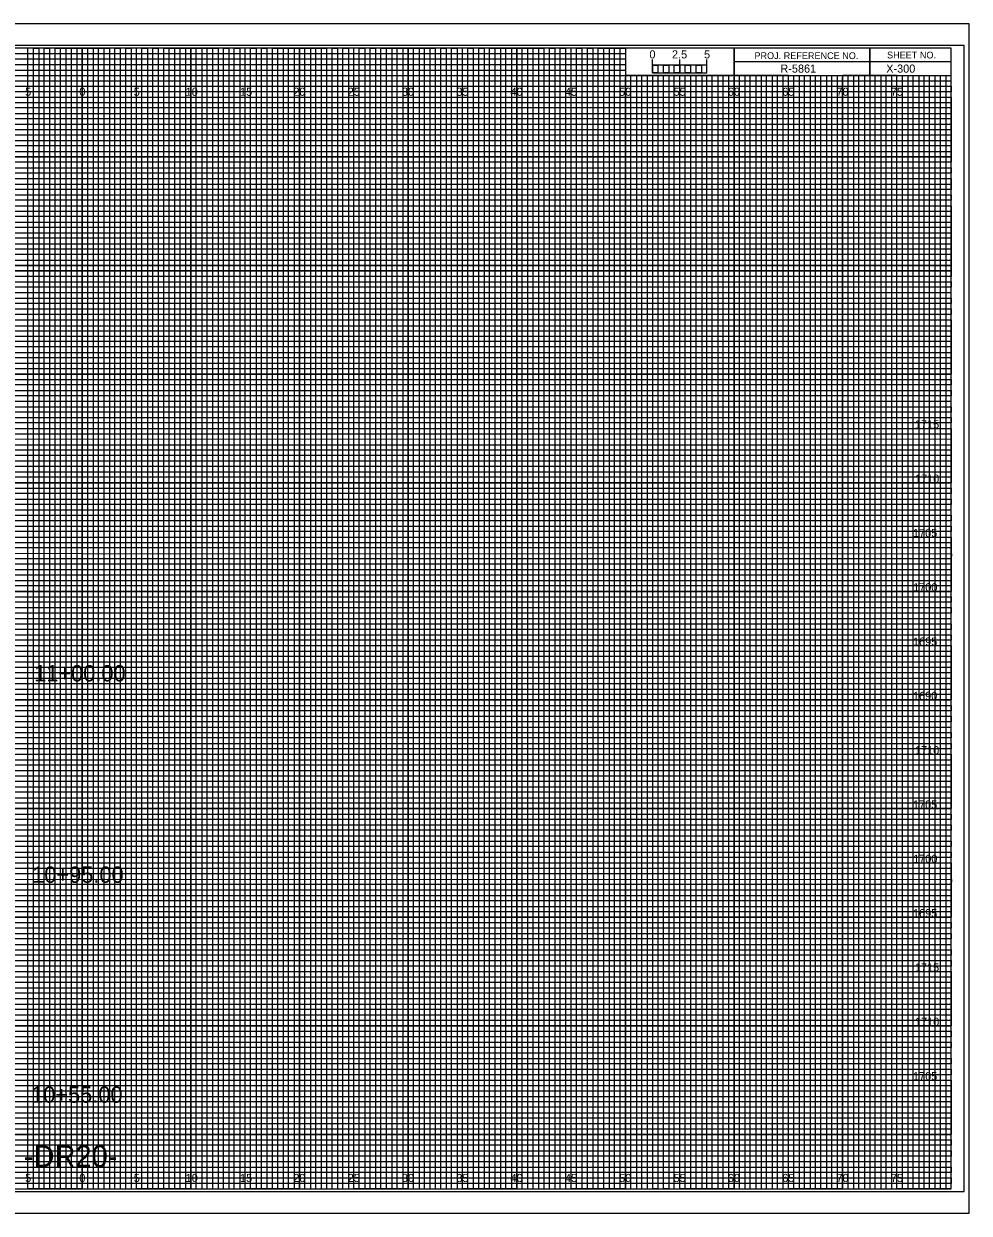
# Model space of a CAD drawing. Extents: x -7 to 162, y -2 to 107.
# Drawn here: x 74.6 to 161.7, y -2.3 to 107.3 of the extents above; entities that cross this region are included whole.
import ezdxf

# ---------------------------------------------------------------- set-up
doc = ezdxf.new("R2010")
doc.units = 0
for name, color, linetype in [('Prop XS Alignment Label', 7, 'Continuous'), ('Prop XS Bar Scale Labels', 7, 'Continuous'), ('Prop XS Elevation Labels', 7, 'Continuous'), ('Prop XS Offset Labels', 7, 'Continuous'), ('Prop XS Project Number', 7, 'Continuous'), ('Prop XS Sheet Number', 7, 'Continuous'), ('Prop XS Station Labels', 7, 'Continuous'), ('Sheet Cross Section CELL', 7, 'Continuous'), ('Sheet Cross Section Grid Major CELL', 7, 'Continuous'), ('Sheet Cross Section Grid Middle CELL', 7, 'Continuous'), ('Sheet Cross Section Grid Minor 1 CELL', 7, 'Continuous'), ('Sheet Cross Section Grid Minor 2 CELL', 7, 'Continuous'), ('Sheet Cross Section Scale CELL', 7, 'Continuous'), ('Sheet Cutting Line CELL', 7, 'Continuous'), ('Sheet DOT Grid CELL', 7, 'Continuous'), ('Sheet Plot Border Inside CELL', 7, 'Continuous'), ('Sheet Plot Border Outside CELL', 7, 'Continuous')]:
    doc.layers.add(name, color=color, linetype=linetype)

msp = doc.modelspace()

# ---------------------------------------------------------------- linework, layer by layer
at = {"layer": 'Sheet Cross Section CELL'}
for p, q in [((152.5, 105), (152.5, 102.5)), ((152.5, 102.5), (152.5, 105)), ((160, 103.75), (140, 103.75)), ((140, 103.75), (140, 102.5)), ((140, 102.5), (160, 102.5))]:
    msp.add_line(p, q, dxfattribs=at)
for points in [[(160, 105), (0, 105), (0, 0), (160, 0)], [(140, 105), (130, 105), (130, 102.52), (140, 102.52)], [(160, 105), (140, 105), (140, 102.5), (160, 102.5)]]:
    msp.add_lwpolyline(points, close=True, dxfattribs=at)
at = {"layer": 'Sheet Cross Section Grid Major CELL'}
for p, q in [((75, 105), (70, 105)), ((75, 0), (75, 105)), ((85, 105), (80, 105)), ((80, 105), (80, 0)), ((85, 0), (85, 105)), ((95, 105), (90, 105)), ((90, 105), (90, 0)), ((95, 0), (95, 105)), ((105, 105), (100, 105)), ((100, 105), (100, 0)), ((105, 0), (105, 105)), ((115, 105), (110, 105)), ((110, 105), (110, 0)), ((115, 0), (115, 105)), ((125, 105), (120, 105)), ((120, 105), (120, 0)), ((125, 0), (125, 105)), ((130, 105), (130, 0)), ((135, 0), (135, 102.5)), ((145, 102.5), (140, 102.5)), ((140, 102.5), (140, 0)), ((145, 0), (145, 102.5)), ((155, 102.5), (150, 102.5)), ((150, 102.5), (150, 0)), ((155, 0), (155, 102.5)), ((80, 0), (75, 0)), ((90, 0), (85, 0)), ((100, 0), (95, 0)), ((110, 0), (105, 0)), ((120, 0), (115, 0)), ((130, 0), (125, 0)), ((140, 0), (135, 0)), ((150, 0), (145, 0)), ((160, 0), (155, 0)), ((160, 0), (160, 0))]:
    msp.add_line(p, q, dxfattribs=at)
for points in [[(0, 100), (160, 100), (160, 95), (0, 95)], [(0, 90), (160, 90), (160, 85), (0, 85)], [(0, 80), (160, 80), (160, 75), (0, 75)], [(0, 70), (160, 70), (160, 65), (0, 65)], [(0, 60), (160, 60), (160, 55), (0, 55)], [(0, 50), (160, 50), (160, 45), (0, 45)], [(0, 40), (160, 40), (160, 35), (0, 35)], [(0, 30), (160, 30), (160, 25), (0, 25)], [(0, 20), (160, 20), (160, 15), (0, 15)], [(0, 10), (160, 10), (160, 5), (0, 5)]]:
    msp.add_lwpolyline(points, dxfattribs=at)
at = {"layer": 'Sheet Cross Section Grid Middle CELL'}
for points in [[(72.5, 0), (77.5, 0), (77.5, 105), (82.5, 105), (82.5, 0), (87.5, 0), (87.5, 105), (92.5, 105), (92.5, 0), (97.5, 0), (97.5, 105), (102.5, 105), (102.5, 0), (107.5, 0), (107.5, 105), (112.5, 105), (112.5, 0), (117.5, 0), (117.5, 105), (122.5, 105), (122.5, 0), (127.5, 0), (127.5, 105), (129.97, 105), (130, 105), (130, 102.5), (132.5, 102.5), (132.5, 0), (137.5, 0), (137.5, 102.5), (142.5, 102.5), (142.5, 0), (147.5, 0), (147.5, 102.5), (152.5, 102.5), (152.5, 0), (157.5, 0), (157.5, 102.5)], [(0, 102.5), (137.5, 102.5)], [(0, 92.5), (160, 92.5), (160, 97.5), (0, 97.5)], [(0, 82.5), (160, 82.5), (160, 87.5), (0, 87.5)], [(0, 72.5), (160, 72.5), (160, 77.5), (0, 77.5)], [(0, 62.5), (160, 62.5), (160, 67.5), (0, 67.5)], [(0, 52.5), (160, 52.5), (160, 57.5), (0, 57.5)], [(0, 42.5), (160, 42.5), (160, 47.5), (0, 47.5)], [(0, 32.5), (160, 32.5), (160, 37.5), (0, 37.5)], [(0, 22.5), (160, 22.5), (160, 27.5), (0, 27.5)], [(0, 12.5), (160, 12.5), (160, 17.5), (0, 17.5)], [(0, 2.5), (160, 2.5), (160, 7.5), (0, 7.5)]]:
    msp.add_lwpolyline(points, dxfattribs=at)
at = {"layer": 'Sheet Cross Section Grid Minor 1 CELL'}
for p, q in [((0, 104.5), (130, 104.5)), ((130, 104.5), (130, 103.99)), ((130, 103.99), (0, 103.99)), ((0, 103.5), (130, 103.5)), ((130, 102.95), (0, 102.95)), ((130, 103.5), (130, 102.95)), ((0, 102), (160, 102))]:
    msp.add_line(p, q, dxfattribs=at)
for points in [[(0, 101.5), (135, 101.5), (160, 101.5), (160, 101), (0, 101)], [(0, 100.5), (160, 100.5), (160, 99.5), (0, 99.5)], [(0, 99), (160, 99), (160, 98.5), (0, 98.49)], [(0, 98), (160, 98), (160, 97), (0, 97)], [(0, 96.5), (160, 96.5), (160, 96), (0, 96)], [(0, 95.5), (160, 95.5), (160, 94.5), (0, 94.5)], [(0, 94), (160, 94), (160, 93.5), (0, 93.5)], [(0, 93), (160, 93), (160, 92), (0, 92)], [(0, 91.5), (160, 91.5), (160, 91), (0, 91)], [(0, 90.5), (160, 90.5), (160, 89.5), (0, 89.5)], [(0, 89), (160, 89), (160, 88.5), (0, 88.5)], [(0, 88), (160, 88), (160, 86.98), (160, 86.5), (160, 86), (0, 86)], [(0, 87), (160, 87), (160, 86.5), (0, 86.5)], [(0, 85.5), (160, 85.5), (160, 84.5), (0, 84.52)], [(0, 84.52), (160, 84.5), (160, 84), (0, 84)], [(0, 83.5), (160, 83.5), (160, 83), (0, 83)], [(0, 82), (160, 82), (160, 81.5), (0, 81.5)], [(0, 81), (160, 81), (160, 80.5), (0, 80.5)], [(-0.04, 79.45), (160, 79.45), (160, 78.94), (-0.04, 78.94)], [(0, 78.5), (160, 78.5), (160, 78), (0, 78)], [(0, 77), (160, 77), (160, 76.5), (0, 76.5)], [(0, 76), (160, 76), (160, 75.5), (0, 75.5)], [(0, 74.5), (160, 74.5), (160, 74), (0, 74)], [(0, 73.5), (160, 73.5), (160, 73), (0, 73)], [(0, 72), (160, 72), (160, 71.5), (0, 71.5)], [(0, 71), (160, 71), (160, 70.5), (0, 70.5)], [(0, 69.5), (160, 69.5), (160, 68.99), (0, 69)], [(0, 68.5), (160, 68.5), (160, 68), (0, 68)], [(0, 67), (160, 67), (160, 66.5), (0, 66.5)], [(0, 66), (160, 66), (160, 65.5), (0, 65.5)], [(0, 64.5), (160, 64.5), (160, 64), (0, 64)], [(0, 63.5), (160, 63.5), (160, 63), (0, 63)], [(0, 62), (160, 62), (160, 61.5), (0, 61.5)], [(0, 61), (160, 61), (160, 60.5), (0, 60.5)], [(0, 59.5), (160, 59.5), (160, 59), (0, 59)], [(0, 58.5), (160.03, 58.45), (160, 58), (0, 58)], [(0, 57), (160, 57), (160, 56.5), (0, 56.5)], [(0, 56), (160, 56), (160, 55.5), (0, 55.5)], [(0, 54.5), (160, 54.5), (160, 54), (0, 54)], [(0, 53.5), (160, 53.5), (160, 53), (0, 53)], [(0, 52), (160, 52), (160, 51.5), (0, 51.5)], [(0, 51), (160, 51), (160, 50.5), (0, 50.5)], [(0, 49.5), (160, 49.5), (160, 49), (0, 49)], [(0, 48.5), (160, 48.5), (160, 48), (0, 48)], [(0, 47), (160, 47), (160, 46.5), (0, 46.5)], [(0, 46), (160, 46), (160, 45.5), (0, 45.5)], [(0, 44.5), (160, 44.5), (160, 44), (0, 44)], [(0, 43.5), (160, 43.5), (160, 43), (0, 43)], [(0, 42), (160, 42), (160, 41.5), (0, 41.5)], [(0, 41), (160, 41), (160, 40.5), (0, 40.5)], [(0, 39.5), (160, 39.5), (160, 38.99), (0, 39)], [(0, 38.5), (160, 38.5), (160, 38), (0, 38)], [(0, 37), (160, 37), (160, 36.5), (0, 36.5)], [(0, 36), (160, 36), (160, 35.5), (0, 35.5)], [(0, 34.5), (160, 34.5), (160, 34), (0, 34)], [(0, 33.5), (160, 33.5), (160, 33), (0, 33)], [(0, 32), (160, 32), (160, 31.5), (0, 31.5)], [(0, 31), (160, 31), (160, 30.5), (0, 30.5)], [(0, 29.5), (160, 29.5), (160, 29), (0, 29)], [(0, 28.5), (160.03, 28.46), (160, 28), (0, 28)], [(0, 27), (160, 27), (160, 26.5), (0, 26.5)], [(0, 26), (160, 26), (160, 25.5), (0, 25.5)], [(0, 24.5), (160, 24.5), (160, 24), (0, 24)], [(0, 23.5), (160, 23.5), (160, 23), (0, 23)], [(0, 22), (160, 22), (160, 21.5), (0, 21.5)], [(0, 21), (160, 21), (160, 20.5), (0, 20.5)], [(0, 19.5), (160, 19.5), (160, 19), (0, 19)], [(0, 18.5), (160, 18.5), (160, 18), (0, 18)], [(0, 17), (160, 17), (160, 16.5), (0, 16.5)], [(0, 16), (160, 16), (160, 15.5), (0, 15.5)], [(0, 14.5), (160, 14.5), (160, 14), (0, 14)], [(0, 13.5), (160, 13.5), (160, 13), (0, 13)], [(0, 12), (160, 12), (160, 11.5), (0, 11.5)], [(0, 11), (160, 11), (160, 10.5), (0, 10.5)], [(0, 9.5), (160, 9.5), (160, 9), (0, 9)], [(0, 8.5), (160, 8.5), (160, 8), (0, 8)], [(0, 7), (160, 7), (160, 6.5), (0, 6.5)], [(0, 6), (160, 6), (160, 5.5), (0, 5.5)], [(0, 4.5), (160, 4.5), (160, 4), (0, 4)], [(0, 3.5), (160, 3.5), (160, 3), (0, 3)], [(0, 2), (160, 2), (160, 1.5), (0, 1.5)], [(0, 1), (160, 1), (160, 0.5), (0, 0.5)]]:
    msp.add_lwpolyline(points, dxfattribs=at)
at = {"layer": 'Sheet Cross Section Grid Minor 2 CELL'}
for p, q in [((133.5, 102.5), (133, 102.5)), ((133, 102.5), (133, 0)), ((133.5, 0), (133.5, 102.5)), ((134.5, 102.5), (134, 102.5)), ((134, 102.5), (134, 0)), ((134.5, 0), (134.5, 102.5)), ((133, 0), (132.5, 0)), ((134, 0), (133.5, 0))]:
    msp.add_line(p, q, dxfattribs=at)
for points in [[(75, 0), (75.5, 0), (75.5, 105), (76, 105), (76, 0)], [(76, 0), (76.5, 0), (76.5, 105), (77, 105), (77, 0)], [(77.5, 0), (78, 0), (78, 105), (78.5, 105), (78.5, 0)], [(78.5, 0), (79, 0), (79, 105), (79.5, 105), (79.5, 0)], [(80, 0), (80.5, 0), (80.5, 105), (81, 105), (81, 0)], [(81, 0), (81.5, 0), (81.5, 105), (82, 105), (82, 0)], [(82.5, 0), (83, 0), (83, 105), (83.5, 105), (83.5, 0)], [(83.5, 0), (84, 0), (84, 105), (84.5, 105), (84.5, 0)], [(85, 0), (85.5, 0), (85.5, 105), (86, 105), (86, 0)], [(86, 0), (86.5, 0), (86.5, 105), (87, 105), (87, 0)], [(87.5, 0), (88, 0), (88, 105), (88.5, 105), (88.5, 0)], [(88.5, 0), (89, 0), (89, 105), (89.5, 105), (89.5, 0)], [(90, 0), (90.5, 0), (90.5, 105), (91, 105), (91, 0)], [(91, 0), (91.5, 0), (91.5, 105), (92, 105), (92, 0)], [(92.5, 0), (93, 0), (93, 105), (93.5, 105), (93.5, 0)], [(93.5, 0), (94, 0), (94, 105), (94.5, 105), (94.5, 0)], [(95, 0), (95.5, 0), (95.5, 105), (96, 105), (96, 0)], [(96, 0), (96.5, 0), (96.5, 105), (97, 105), (97, 0)], [(97.5, 0), (98, 0), (98, 105), (98.5, 105), (98.5, 0)], [(98.5, 0), (99, 0), (99, 105), (99.5, 105), (99.5, 0)], [(100, 0), (100.5, 0), (100.5, 105), (101, 105), (101, 0)], [(101, 0), (101.5, 0), (101.5, 105), (102, 105), (102, 0)], [(102.5, 0), (103, 0), (103, 105), (103.5, 105), (103.5, 0)], [(103.5, 0), (104, 0), (104, 105), (104.5, 105), (104.5, 0)], [(105, 0), (105.5, 0), (105.5, 105), (106, 105), (106, 0)], [(106, 0), (106.5, 0), (106.5, 105), (107, 105), (107, 0)], [(107.5, 0), (108, 0), (108, 105), (108.5, 105), (108.5, 0)], [(108.5, 0), (109, 0), (109, 105), (109.5, 105), (109.5, 0)], [(110, 0), (110.5, 0), (110.5, 105), (111, 105), (111, 0)], [(111, 0), (111.5, 0), (111.5, 105), (112, 105), (112, 0)], [(112.5, 0), (113, 0), (113, 105), (113.5, 105), (113.5, 0)], [(113.5, 0), (114, 0), (114, 105), (114.5, 105), (114.5, 0)], [(115, 0), (115.5, 0), (115.5, 105), (116, 105), (116, 0)], [(116, 0), (116.5, 0), (116.5, 105), (117, 105), (117, 0)], [(117.5, 0), (118, 0), (118, 105), (118.5, 105), (118.5, 0)], [(118.5, 0), (119, 0), (119, 105), (119.5, 105), (119.5, 0)], [(120, 0), (120.5, 0), (120.5, 105), (121, 105), (121, 0)], [(121, 0), (121.5, 0), (121.5, 105), (122, 105), (122, 0)], [(122.5, 0), (123, 0), (123, 105), (123.5, 105), (123.5, 0)], [(123.5, 0), (124, 0), (124, 105), (124.5, 105), (124.5, 0)], [(125, 0), (125.5, 0), (125.5, 105), (126, 105), (126, 0)], [(126, 0), (126.5, 0), (126.5, 105), (127, 105), (127, 0)], [(127.5, 0), (128, 0), (128, 105), (128.5, 105), (128.5, 0)], [(128.5, 0), (129, 0), (129, 105), (129.5, 105), (129.5, 0)], [(130, 0), (130.5, 0), (130.5, 102.5), (131.01, 102.5), (131.01, 0)], [(131, 0), (131.5, 0), (131.5, 102.5), (132, 102.5), (132, 0)], [(135, 0), (135.49, 0), (135.49, 102.5), (136, 102.5), (136, 0)], [(136, 0), (136.5, 0), (136.5, 102.5), (137.03, 102.5), (137.03, 0)], [(137.5, 0), (138, 0), (138, 102.5), (138.5, 102.5), (138.5, 0)], [(138.5, 0), (139, 0), (139, 102.5), (139.5, 102.5), (139.5, 0)], [(140, 0), (140.5, 0), (140.5, 102.5), (141, 102.5), (141, 0)], [(141, 0), (141.5, 0), (141.5, 102.5), (142, 102.5), (142, 0)], [(142.5, 0), (143, 0), (143, 102.5), (143.5, 102.5), (143.5, 0)], [(143.5, 0), (144, 0), (144, 102.5), (144.5, 102.5), (144.5, 0)], [(145, 0), (145.5, 0), (145.5, 102.5), (146, 102.5), (146, 0)], [(146, 0), (146.5, 0), (146.5, 102.5), (147, 102.5), (147, 0)], [(147.5, 0), (148, 0), (148, 102.5), (148.5, 102.5), (148.5, 0)], [(148.5, 0), (149, 0), (149, 102.5), (149.5, 102.5), (149.5, 0)], [(150, 0), (150.5, 0), (150.5, 102.5), (151, 102.5), (151, 0)], [(151, 0), (151.5, 0), (151.5, 102.5), (152, 102.5), (152, 0)], [(152.5, 0), (153, 0), (153, 102.5), (153.5, 102.5), (153.5, 0)], [(153.5, 0), (154, 0), (154, 102.5), (154.5, 102.5), (154.5, 0)], [(155, 0), (155.5, 0), (155.5, 102.5), (156, 102.5), (156, 0)], [(156, 0), (156.5, 0), (156.5, 102.5), (157, 102.5), (157, 0)], [(157.5, 0), (158, 0), (158, 102.5), (158.5, 102.5), (158.5, 0)], [(158.5, 0), (159, 0), (159, 102.5), (159.5, 102.5), (159.5, 0)]]:
    msp.add_lwpolyline(points, dxfattribs=at)
at = {"layer": 'Sheet Cross Section Scale CELL'}
for p, q in [((132.5, 102.75), (132.5, 103.95)), ((132.5, 103.45), (132.5, 103.95)), ((135, 102.75), (135, 103.95)), ((137.5, 102.75), (137.5, 103.95)), ((137.5, 103.45), (137.5, 103.95))]:
    msp.add_line(p, q, dxfattribs=at)
for points in [[(137.5, 103.45), (132.5, 103.45), (132.5, 102.75), (137.5, 102.75)], [(132.5, 103.45), (133, 103.45), (133, 102.75), (132.5, 102.75)], [(133.5, 103.45), (134, 103.45), (134, 102.75), (133.5, 102.75)], [(134.5, 103.45), (135, 103.45), (135, 102.75), (134.5, 102.75)], [(135.5, 103.45), (136, 103.45), (136, 102.75), (135.5, 102.75)], [(136.5, 103.45), (137, 103.45), (137, 102.75), (136.5, 102.75)]]:
    msp.add_lwpolyline(points, close=True, dxfattribs=at)
at = {"layer": 'Sheet Cutting Line CELL'}
for p, q in [((161.65, 107.25), (-6.7, 107.25)), ((-6.7, -2.25), (161.65, -2.25))]:
    msp.add_line(p, q, dxfattribs=at)
at = {"layer": 'Sheet DOT Grid CELL'}
for p, q in [((75, 0), (75, 105)), ((80, 0), (80, 105)), ((85, 0), (85, 105)), ((90, 0), (90, 105)), ((95, 0), (95, 105)), ((100, 0), (100, 105)), ((105, 0), (105, 105)), ((110, 0), (110, 105)), ((115, 0), (115, 105)), ((120, 0), (120, 105)), ((125, 0), (125, 105)), ((130, 0), (130, 102.34)), ((135, 0), (135, 102.34)), ((140, 0), (140, 102.34)), ((145, 0), (145, 102.34)), ((150, 0), (150, 102.34)), ((155, 0), (155, 102.34)), ((0, 100), (160, 100)), ((0, 95), (160, 95)), ((0, 90), (160, 90)), ((0, 85), (160, 85)), ((0, 80), (160, 80)), ((0, 75), (160, 75)), ((0, 70), (160, 70)), ((0, 65), (160, 65)), ((0, 60), (160, 60)), ((0, 55), (160, 55)), ((0, 50), (160, 50)), ((0, 45), (160, 45)), ((0, 40), (160, 40)), ((0, 35), (160, 35)), ((0, 30), (160, 30)), ((0, 25), (160, 25)), ((0, 20), (160, 20)), ((0, 15), (160, 15)), ((0, 10), (160, 10)), ((0, 5), (160, 5))]:
    msp.add_line(p, q, dxfattribs=at)
at = {"layer": 'Sheet Plot Border Inside CELL'}
msp.add_lwpolyline([(-5.4, -0.25), (161.2, -0.25), (161.2, 105.25), (-5.4, 105.25)], close=True, dxfattribs=at)
at = {"layer": 'Sheet Plot Border Outside CELL'}
msp.add_lwpolyline([(-6.7, -2.25), (161.65, -2.25), (161.65, 107.25), (-6.7, 107.25)], close=True, dxfattribs=at)

# ---------------------------------------------------------------- texts
at = {"layer": 'Prop XS Alignment Label'}
msp.add_text('-DR20-', height=2, dxfattribs=at).set_placement((74.62, 2))
at = {"layer": 'Prop XS Bar Scale Labels'}
for s, p in [('2.5', (134.29, 104.06)), ('5', (137.24, 104.06))]:
    msp.add_text(s, height=0.75, dxfattribs=at).set_placement(p)
at = {"layer": 'Prop XS Elevation Labels'}
for s, p in [('1715', (156.65, 70)), ('1710', (156.66, 65)), ('1705', (156.48, 60)), ('1700', (156.49, 55)), ('1695', (156.48, 50)), ('1690', (156.48, 45)), ('1710', (156.66, 40)), ('1705', (156.48, 35)), ('1700', (156.49, 30)), ('1695', (156.48, 25)), ('1715', (156.65, 20)), ('1710', (156.66, 15)), ('1705', (156.48, 10))]:
    msp.add_text(s, height=0.75, dxfattribs=at).set_placement(p)
at = {"layer": 'Prop XS Offset Labels'}
for s, p in [('5', (74.74, 100.62)), ('0', (79.73, 100.62)), ('0', (79.73, 100.62)), ('5', (84.74, 100.62)), ('10', (89.52, 100.62)), ('15', (94.53, 100.62)), ('20', (99.43, 100.62)), ('25', (104.44, 100.62)), ('30', (109.43, 100.62)), ('35', (114.44, 100.62)), ('40', (119.43, 100.62)), ('45', (124.44, 100.62)), ('50', (129.43, 100.62)), ('55', (134.44, 100.62)), ('60', (139.43, 100.62)), ('65', (144.44, 100.62)), ('70', (149.43, 100.62)), ('75', (154.44, 100.62)), ('5', (74.74, 0.62)), ('0', (79.73, 0.62)), ('0', (79.73, 0.62)), ('5', (84.74, 0.62)), ('10', (89.52, 0.62)), ('15', (94.53, 0.62)), ('20', (99.43, 0.62)), ('25', (104.44, 0.62)), ('30', (109.43, 0.62)), ('35', (114.44, 0.62)), ('40', (119.43, 0.62)), ('45', (124.44, 0.62)), ('50', (129.43, 0.62)), ('55', (134.44, 0.62)), ('60', (139.43, 0.62)), ('65', (144.44, 0.62)), ('70', (149.43, 0.62)), ('75', (154.44, 0.62))]:
    msp.add_text(s, height=0.75, dxfattribs=at).set_placement(p)
at = {"layer": 'Prop XS Project Number'}
msp.add_text('R-5861', height=0.75, dxfattribs=at).set_placement((144.27, 102.75))
at = {"layer": 'Prop XS Sheet Number'}
msp.add_text('X-300', height=0.75, dxfattribs=at).set_placement((154.01, 102.75))
at = {"layer": 'Prop XS Station Labels'}
for s, p in [('11+00.00', (75.57, 46.71)), ('10+95.00', (75.39, 28.17)), ('10+55.00', (75.29, 7.92))]:
    msp.add_text(s, height=1.5, dxfattribs=at).set_placement(p)
at = {"layer": 'Sheet Cross Section CELL'}
for s, p in [('PROJ. REFERENCE NO.', (141.88, 104)), ('SHEET NO.', (154.09, 104.06))]:
    msp.add_text(s, height=0.625, dxfattribs=at).set_placement(p)
at = {"layer": 'Sheet Cross Section Scale CELL'}
msp.add_text('0', height=0.75, dxfattribs=at).set_placement((132.21, 104.06))

doc.saveas('drawing.dxf')
